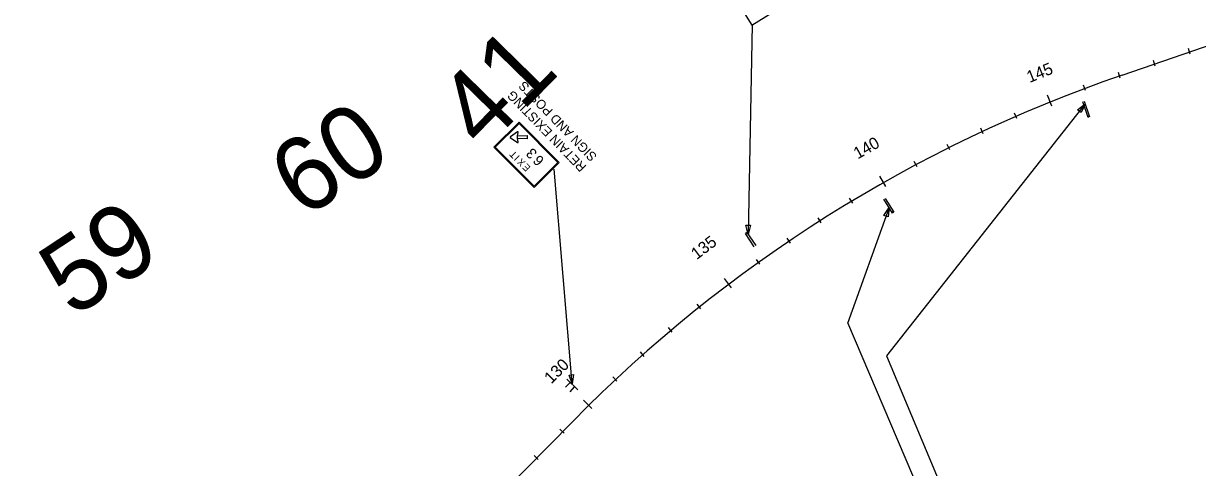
# Model space of a CAD drawing. Extents: x -5665 to 1997148, y 4 to 827579.
# Drawn here: x 1962258 to 1965427, y 800219 to 801417 of the extents above; entities that cross this region are included whole.
import ezdxf

# ---------------------------------------------------------------- set-up
doc = ezdxf.new("R2010")
doc.units = 0
for name, color, linetype in [('RD_HC_CL_Rel', 7, 'Continuous'), ('RD_HC_Data_Tic_Rel', 7, 'Continuous'), ('RD_HC_TX_Rel_Sta50', 7, 'Continuous'), ('RD_SHT_TX', 7, 'Continuous'), ('TR SN EXTRUDED PANEL SIGNS- MOUNTED OVERHEAD', 7, 'Continuous')]:
    doc.layers.add(name, color=color, linetype=linetype)

msp = doc.modelspace()

# ---------------------------------------------------------------- linework, layer by layer
at = {"layer": 'RD_HC_CL_Rel'}
for p, q in [((1965223.3, 801278), (1967465.8, 802047.7)), ((1957622, 794124.4), (1963740.1, 800343.8))]:
    msp.add_line(p, q, dxfattribs=at)
msp.add_arc((1966463.2, 797665.2), 3819.7, 108.942, 135.4705, dxfattribs=at)
at = {"layer": 'RD_HC_Data_Tic_Rel'}
for p, q in [((1965407.4, 801334.9), (1965402.3, 801350)), ((1965312.9, 801302.4), (1965307.7, 801317.6)), ((1965218.3, 801270), (1965213.1, 801285.1)), ((1965124.4, 801236.2), (1965118.7, 801251.1)), ((1965033.6, 801194.3), (1965021.6, 801224)), ((1964939.3, 801161.2), (1964932.9, 801175.9)), ((1964848.3, 801120.1), (1964841.5, 801134.6)), ((1964758.4, 801076.6), (1964751.3, 801091)), ((1964669.7, 801030.8), (1964662.2, 801045)), ((1964585.2, 800977.5), (1964569.4, 801005.4)), ((1964496, 800932.4), (1964487.8, 800946.1)), ((1964411.2, 800879.8), (1964402.6, 800893.2)), ((1964327.7, 800824.9), (1964318.8, 800838.2)), ((1964245.7, 800768), (1964236.4, 800781)), ((1964168.9, 800704.1), (1964149.6, 800729.6)), ((1964086.4, 800647.7), (1964076.4, 800660.2)), ((1964009.1, 800584.4), (1963998.8, 800596.7)), ((1963933.5, 800519.2), (1963922.9, 800531.1)), ((1963859.7, 800452), (1963848.8, 800463.7)), ((1963791.9, 800378.6), (1963769.4, 800401.4)), ((1963717.2, 800312), (1963705.8, 800323.2)), ((1963647.1, 800240.7), (1963635.7, 800251.9))]:
    msp.add_line(p, q, dxfattribs=at)
at = {"layer": 'TR SN EXTRUDED PANEL SIGNS- MOUNTED OVERHEAD'}
for p, q in [((1964224.3, 801414.8), (1964213.9, 800848.4)), ((1965123.3, 801200.3), (1964587.4, 800520.3)), ((1965131.2, 801164), (1965117.1, 801206)), ((1965120.8, 801207.6), (1965135.2, 801165.3)), ((1963591.4, 801124.7), (1963592.1, 801123.7)), ((1963592.1, 801123.7), (1963593.2, 801123.5)), ((1963571.8, 801109.7), (1963572.5, 801110.7)), ((1963572.5, 801110.7), (1963571.9, 801111.7)), ((1963592, 801097.6), (1963591.4, 801096.6)), ((1963593.2, 801097.9), (1963592, 801097.6)), ((1963739, 800444.7), (1963690.3, 801024.2)), ((1964603.4, 800905.6), (1964580.3, 800943.2)), ((1964583.9, 800945.5), (1964607.2, 800908.4)), ((1964594.1, 800920.9), (1964481.8, 800608)), ((1964230.2, 800815.1), (1964206.2, 800850.9)), ((1964210.2, 800853.8), (1964234.3, 800818.7)), ((1963754.2, 800429.1), (1963724.3, 800457.3)), ((1963720.7, 800436.1), (1963732.9, 800449.1)), ((1963733.1, 800423.6), (1963745.3, 800436.6))]:
    msp.add_line(p, q, dxfattribs=at)
for points in [[(1964325.3, 801476.2), (1964171.5, 801722), (1964069.8, 801658.4), (1964223.6, 801412.5), (1964325.3, 801476.2), (1964325.3, 801476.2), (1964325.3, 801476.2)], [(1965132.3, 801165.3), (1965132.8, 801165.1), (1965133.3, 801165.3), (1965133.7, 801165.7), (1965133.8, 801166.2), (1965133.6, 801166.8), (1965133.1, 801167.1), (1965132.6, 801167.1), (1965132.1, 801166.8), (1965131.8, 801166.3), (1965131.8, 801165.8), (1965132.2, 801165.3), (1965132.3, 801165.3)], [(1965132.4, 801165.4), (1965132.9, 801165.3), (1965133.3, 801165.5), (1965133.6, 801165.9), (1965133.6, 801166.4), (1965133.2, 801166.8), (1965132.7, 801166.9), (1965132.3, 801166.7), (1965132, 801166.3), (1965132, 801165.8), (1965132.4, 801165.4)], [(1965132.5, 801165.6), (1965132.9, 801165.5), (1965133.3, 801165.7), (1965133.4, 801166.1), (1965133.2, 801166.5), (1965132.8, 801166.7), (1965132.4, 801166.6), (1965132.2, 801166.2), (1965132.3, 801165.8), (1965132.5, 801165.6)], [(1965132.6, 801165.8), (1965132.9, 801165.7), (1965133.2, 801166), (1965133.1, 801166.3), (1965132.9, 801166.5), (1965132.5, 801166.4), (1965132.4, 801166.1), (1965132.6, 801165.8), (1965132.6, 801165.8)], [(1965132.7, 801165.9), (1965132.9, 801166), (1965133, 801166.2), (1965132.8, 801166.3), (1965132.6, 801166.2), (1965132.7, 801165.9)], [(1964604.2, 800907.3), (1964604.7, 800907.1), (1964605.2, 800907.3), (1964605.6, 800907.7), (1964605.7, 800908.3), (1964605.5, 800908.8), (1964605, 800909.1), (1964604.5, 800909.1), (1964604, 800908.9), (1964603.7, 800908.4), (1964603.7, 800907.8), (1964604.1, 800907.3), (1964604.2, 800907.3)], [(1964604.3, 800907.5), (1964604.8, 800907.3), (1964605.2, 800907.5), (1964605.5, 800908), (1964605.4, 800908.5), (1964605.1, 800908.8), (1964604.6, 800909), (1964604.2, 800908.8), (1964603.9, 800908.3), (1964603.9, 800907.8), (1964604.3, 800907.5)], [(1964604.4, 800907.6), (1964604.8, 800907.6), (1964605.2, 800907.8), (1964605.3, 800908.2), (1964605.1, 800908.6), (1964604.7, 800908.8), (1964604.3, 800908.6), (1964604.1, 800908.3), (1964604.2, 800907.8), (1964604.4, 800907.6)], [(1964604.5, 800907.8), (1964604.8, 800907.8), (1964605.1, 800908), (1964605, 800908.4), (1964604.8, 800908.6), (1964604.4, 800908.4), (1964604.3, 800908.1), (1964604.5, 800907.8), (1964604.5, 800907.8)], [(1964604.6, 800908), (1964604.8, 800908), (1964604.9, 800908.2), (1964604.7, 800908.4), (1964604.5, 800908.2), (1964604.6, 800908)], [(1964208.1, 800851), (1964208.6, 800850.9), (1964209.2, 800851), (1964209.5, 800851.5), (1964209.6, 800852), (1964209.4, 800852.5), (1964208.9, 800852.8), (1964208.4, 800852.9), (1964207.9, 800852.6), (1964207.6, 800852.1), (1964207.7, 800851.5), (1964208, 800851.1), (1964208.1, 800851)], [(1964208.2, 800851.2), (1964208.7, 800851.1), (1964209.1, 800851.3), (1964209.4, 800851.7), (1964209.4, 800852.2), (1964209, 800852.6), (1964208.6, 800852.7), (1964208.1, 800852.5), (1964207.8, 800852.1), (1964207.9, 800851.6), (1964208.2, 800851.2)], [(1964208.3, 800851.4), (1964208.7, 800851.3), (1964209.1, 800851.5), (1964209.2, 800851.9), (1964209.1, 800852.3), (1964208.7, 800852.5), (1964208.2, 800852.4), (1964208, 800852), (1964208.1, 800851.6), (1964208.3, 800851.4)], [(1964208.4, 800851.5), (1964208.8, 800851.5), (1964209, 800851.7), (1964209, 800852.1), (1964208.7, 800852.3), (1964208.3, 800852.2), (1964208.2, 800851.9), (1964208.4, 800851.6), (1964208.4, 800851.5)], [(1964208.5, 800851.7), (1964208.7, 800851.7), (1964208.8, 800852), (1964208.6, 800852.1), (1964208.4, 800851.9), (1964208.5, 800851.7)], [(1964481.8, 800610.6), (1964773.7, 799926.3), (1964782.2, 799571.1)], [(1964587.4, 800520.3), (1965083.1, 799338.2)]]:
    msp.add_lwpolyline(points, dxfattribs=at)
for points in [[(1965112.8, 801177), (1965103.1, 801184.7), (1965123.3, 801200.3)], [(1963635.8, 800974.7), (1963527.4, 801083.4), (1963595.3, 801151.1), (1963703.7, 801042.4)], [(1963531, 801083.4), (1963595.3, 801147.5), (1963700, 801042.4), (1963635.8, 800978.3)], [(1963572.5, 801110.7), (1963571.8, 801109.7), (1963591.4, 801096.6), (1963592, 801097.6), (1963593.2, 801097.9), (1963590.9, 801107.2), (1963590.9, 801114.2), (1963593.2, 801123.5), (1963592.1, 801123.7), (1963591.4, 801124.7), (1963571.9, 801111.7), (1963572.5, 801110.7)], [(1963617, 801115.3), (1963617, 801105.9), (1963590.9, 801107.2), (1963590.9, 801114.2), (1963617, 801115.3)], [(1964591.6, 800895.4), (1964579.9, 800899.5), (1964594.1, 800920.9)], [(1964207.9, 800873.3), (1964220.3, 800873.2), (1964213.9, 800848.4)], [(1963730.4, 800468.8), (1963742.7, 800470), (1963739, 800444.7)]]:
    msp.add_lwpolyline(points, close=True, dxfattribs=at)
for centre, start, end in [((1963592.1, 801123.7), 345.9462, 123.73), ((1963572.5, 801110.7), 123.73, 236.0858), ((1963592, 801097.6), 236.0862, 13.8705)]:
    msp.add_arc(centre, 1.17, start, end, dxfattribs=at)

# ---------------------------------------------------------------- texts
at = {"layer": 'RD_HC_TX_Rel_Sta50'}
for s, rotation, p in [('145', 22.0518, (1964973.5, 801256.8)), ('140', 29.5518, (1964509.6, 801050.5)), ('135', 37.0518, (1964074.9, 800778.9)), ('130', 44.5518, (1963682.2, 800443.3))]:
    msp.add_text(s, height=32, rotation=rotation, dxfattribs=at).set_placement(p)
at = {"layer": 'RD_SHT_TX'}
for s, rotation, p in [('41', 45.6376, (1963499.7, 801071.4)), ('60', 33.3906, (1963012.2, 800888)), ('59', 33.3906, (1962390.3, 800621.4))]:
    msp.add_text(s, height=200, rotation=rotation, dxfattribs=at).set_placement(p)
at = {"layer": 'TR SN EXTRUDED PANEL SIGNS- MOUNTED OVERHEAD'}
for s, height, rotation, p in [('SIGN AND POSTS', 25, 134.078, (1963807.4, 801059.9)), ('RETAIN EXISTING', 25, 134.078, (1963778.7, 801032.1)), ('T', 18.7, 134.9081, (1963592.1, 801065.1)), ('I', 18.7, 134.9081, (1963598.4, 801058.7)), ('3', 28.1, 134.9081, (1963646.2, 801068.9)), ('6', 28.1, 134.9081, (1963665.1, 801050)), ('X', 18.7, 134.9081, (1963613.9, 801043.2)), ('E', 18.7, 134.9081, (1963627.7, 801029.4))]:
    msp.add_text(s, height=height, rotation=rotation, dxfattribs=at).set_placement(p)

doc.saveas('drawing.dxf')
